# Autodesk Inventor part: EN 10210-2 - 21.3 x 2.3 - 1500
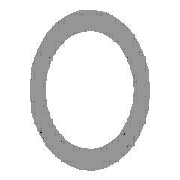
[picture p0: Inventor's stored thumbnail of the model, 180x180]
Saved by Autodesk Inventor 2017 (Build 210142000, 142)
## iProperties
Created: 2017-11
Part Number: EN 10210-2 - 21.3 x 2.3 - 1500
Material: Steel, Mild
Description: Pipe
Document SubType Name: Modeling
Standard: DIN
Designer: iusti
Standard Revision: 2006-07
Standards Organization: DIN
Language: en-US
Size Designation: 21.3 x 2.3
Categories: <MemberInstance><Categories><Category DisplayName="Structural Shapes" InternalName="089c4875-fa83-4c05-b084-43b9cc11f5ed" Mnemonic="GRDR"><CategoryParameter Dis
Stock Number: 21.3 x 2.3
Density: 7.85 g/cm^3
Appearance: Semi-Polished
_CCFamilyMember: 1
_CCFamilyDisplayName: DIN EN 10210-2 - Pipe
_FrameMemberDoc: Frame Member File
_Version: 15.0.0
_GetPNFromCC: 1
IsCustomPart: 1
Author: iusti
G_L: 1500.000 mm
G_W: 21.300 mm
G_H: 21.300 mm
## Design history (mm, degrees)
node "Start plane"
node "End plane"
sketch "Sketch"
  geometry: C1 r 8.35 at (0, 0); C2 r 10.65 at (0, 0); 2 further points
  constraints: 3 coincident, 2 centre point
  dimensions: "d0" = 21.3 diameter of C2 (= G_H); "d1" = 2.3 radial gap between concentric circles of C2 C1 (= G_T)
extrude "Body" new body sketch "Sketch" stored distance "d2" = 1500 (= G_L); taper "d3" = 0 deg
node "Driven Length"
  sketch "Sketch3"
    geometry: L1 (0, 0)-(10, 0) reference
    constraints: 2 end point, 1 horizontal
  workplane "Work Plane3"
  sketch "Sketch4"
    geometry: L1 (-2, 0)-(12, 0) reference; L2 (-2, 1500)-(12, 1500) reference
    dimensions: "d7" = 1500 distance between parallel lines of L1 L2 (derived)
body "Solid1"
other parameters: "G_H" = 21.3 [user parameter; used in 1 equation term], "G_T" = 2.3 [user parameter; used in 1 equation term], "G_L" = 1500 (= d7) [user parameter; used in 1 equation term], "G_OFFSET_START" = 0 [user parameter; used in 1 equation term], "G_OFFSET_END" = 0 [user parameter; used in 1 equation term], "d4" = 0 (computed from G_OFFSET_START), "d6" = 90 deg
